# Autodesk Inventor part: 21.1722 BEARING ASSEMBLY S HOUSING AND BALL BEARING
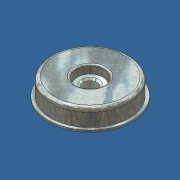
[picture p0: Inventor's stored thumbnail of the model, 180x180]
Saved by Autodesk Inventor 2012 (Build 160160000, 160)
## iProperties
Created: 2007-07
Part Number: 21.1722 BEARING ASSEMBLY S HOUSING AND BALL BEARING
Material: Steel
Document SubType Name: Modeling
Designer: Andy Moles
Density: 7.85 g/cm^3
Mass: 76.4243 g
Surface Area: 85.8946 cm^2
Volume: 9.73559 cm^3
Author: Andy Moles
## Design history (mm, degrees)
feature "Base1"
body "Solid1"
